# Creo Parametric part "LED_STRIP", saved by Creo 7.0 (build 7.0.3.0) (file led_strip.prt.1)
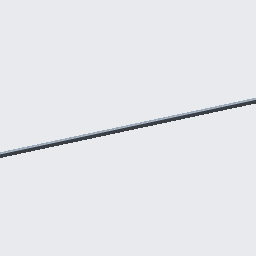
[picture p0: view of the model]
Units: millimeter Kilogram Sec (mmKs); MM, KILOGRAM, SECS

Created from: XX_SOLID_PART_MMKS_ABS.PRT

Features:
  1. coordinate system
  2. datum plane "RIGHT"
  3. datum plane "TOP"
  4. datum plane "FRONT"
  5. extrusion "Extrude 1"
  6. round "Round 1"

Surfaces: 6 plane, 2 cylinder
